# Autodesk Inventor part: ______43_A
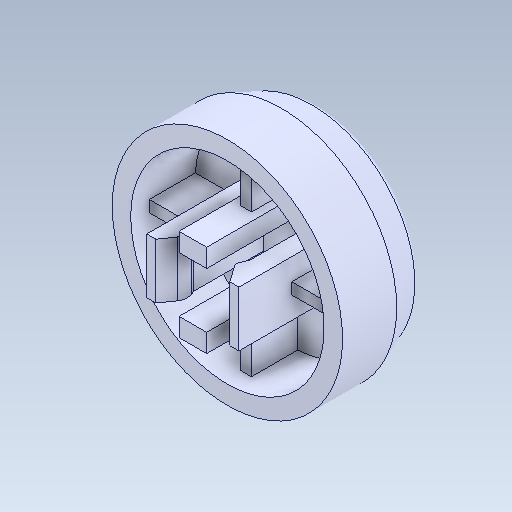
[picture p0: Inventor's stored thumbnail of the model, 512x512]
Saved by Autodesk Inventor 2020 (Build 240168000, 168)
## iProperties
Created: 2017-09
Part Number: ______43_A
Material: Générique
Document SubType Name: Modeling
Designer: bruno
Density: 1 g/cm^3
Appearance: Par défaut
Author: bruno
Sending System: SolidWorks 2016
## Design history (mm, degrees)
feature "Importée1"
node "Solide1"
